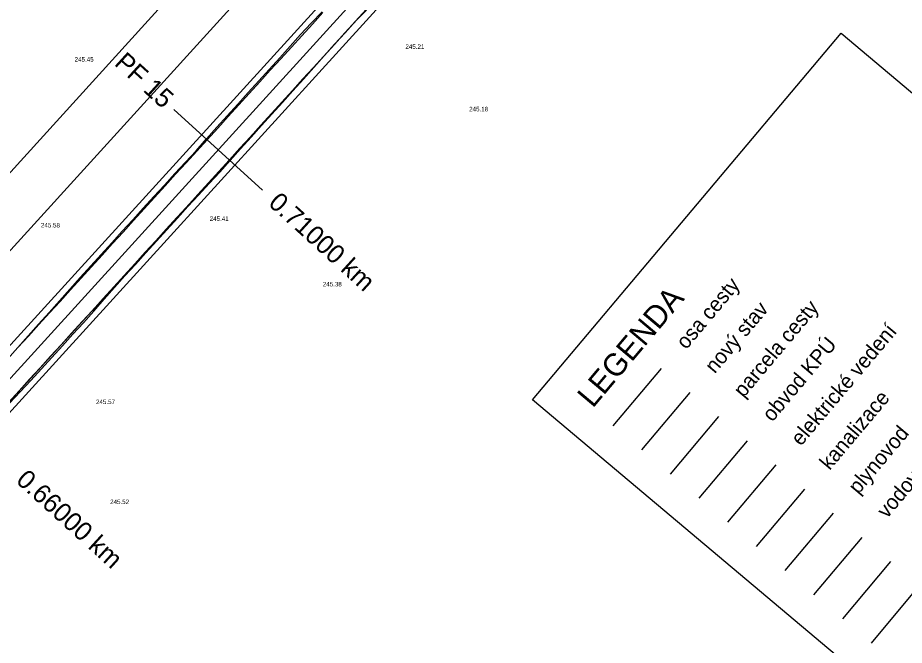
# Model space of a CAD drawing. Extents: x -555887 to -552101, y -1100251 to -1096546.
# Drawn here: x -554433.8 to -554315.6, y -1097133.2 to -1097049.5 of the extents above; entities that cross this region are included whole.
import ezdxf

# ---------------------------------------------------------------- set-up
doc = ezdxf.new("R2010")
doc.units = 0
for name, color, linetype in [('IP_návrh', 7, 'Continuous'), ('PARCELY_cesty', 7, 'Continuous'), ('POLYGONY_SITUACE_PF', 7, 'Continuous'), ('POLYGONY_SITUACE_PF_POPISY', 7, 'Continuous'), ('POLYGONY_SITUACE_PO', 7, 'Continuous'), ('ram_VC2', 7, 'Continuous'), ('Výškopis', 7, 'Continuous'), ('zájem', 7, 'Continuous')]:
    doc.layers.add(name, color=color, linetype=linetype)

msp = doc.modelspace()

# ---------------------------------------------------------------- linework, layer by layer
at = {"layer": 'IP_návrh'}
msp.add_line((-554875.9, -1097565.92), (-554275.99, -1096905.69), dxfattribs=at)
at = {"layer": 'PARCELY_cesty'}
for points in [[(-554879.07, -1097590.15), (-554550.67, -1097229.32), (-554531.76, -1097208.54), (-554275.81, -1096927.3), (-554273.04, -1096923.94), (-554268.63, -1096916.51), (-554265.12, -1096907.97), (-554264.18, -1096901.52)], [(-554875.85, -1097577.71), (-554629.16, -1097306.65), (-554626.42, -1097299.8), (-554612.94, -1097285.13), (-554606.19, -1097281.41), (-554359.61, -1097010.48), (-554356.78, -1097004.21), (-554343, -1096989.28), (-554337.66, -1096986.36), (-554280.34, -1096923.38), (-554277.96, -1096920.48), (-554274.11, -1096913.98), (-554271.59, -1096906.68), (-554270.35, -1096901.41)]]:
    msp.add_lwpolyline(points, dxfattribs=at)
at = {"layer": 'POLYGONY_SITUACE_PF'}
for p, q in [((-554412.99, -1097061.7), (-554407.07, -1097067.08)), ((-554407.07, -1097067.08), (-554401.16, -1097072.47))]:
    msp.add_line(p, q, dxfattribs=at)
at = {"layer": 'POLYGONY_SITUACE_PO'}
for p, q in [((-554884.96, -1097592.18), (-554278.08, -1096925.34)), ((-554878.71, -1097588.28), (-554338.29, -1096994.47)), ((-554394.68, -1097050.19), (-554393.24, -1097048.68)), ((-554394.53, -1097050.33), (-554393.13, -1097048.79)), ((-554394.53, -1097050.33), (-554393.13, -1097048.79)), ((-554388.77, -1097049.94), (-554387.37, -1097048.4)), ((-554388.76, -1097049.94), (-554387.3, -1097048.46)), ((-554390.17, -1097051.48), (-554388.77, -1097049.94)), ((-554390.14, -1097051.44), (-554388.76, -1097049.94)), ((-554396.11, -1097051.7), (-554394.68, -1097050.19)), ((-554395.93, -1097051.87), (-554394.53, -1097050.33)), ((-554395.93, -1097051.87), (-554394.53, -1097050.33)), ((-554397.5, -1097053.26), (-554396.11, -1097051.7)), ((-554397.33, -1097053.41), (-554395.93, -1097051.87)), ((-554397.33, -1097053.41), (-554395.93, -1097051.87)), ((-554391.57, -1097053.02), (-554390.17, -1097051.48)), ((-554391.56, -1097053.03), (-554390.19, -1097051.5)), ((-554390.19, -1097051.5), (-554390.17, -1097051.48)), ((-554390.17, -1097051.48), (-554390.14, -1097051.44)), ((-554398.88, -1097054.82), (-554397.5, -1097053.26)), ((-554398.74, -1097054.95), (-554397.33, -1097053.41)), ((-554398.74, -1097054.95), (-554397.33, -1097053.41)), ((-554392.97, -1097054.56), (-554391.57, -1097053.02)), ((-554392.95, -1097054.58), (-554391.56, -1097053.03)), ((-554394.38, -1097056.1), (-554392.97, -1097054.56)), ((-554394.34, -1097056.13), (-554392.95, -1097054.58)), ((-554400.27, -1097056.37), (-554398.88, -1097054.82)), ((-554400.14, -1097056.49), (-554398.74, -1097054.95)), ((-554400.14, -1097056.49), (-554398.74, -1097054.95)), ((-554401.68, -1097057.91), (-554400.27, -1097056.37)), ((-554401.54, -1097058.03), (-554400.14, -1097056.49)), ((-554401.54, -1097058.03), (-554400.14, -1097056.49)), ((-554395.78, -1097057.64), (-554394.38, -1097056.1)), ((-554395.73, -1097057.68), (-554394.34, -1097056.13)), ((-554403.08, -1097059.45), (-554401.68, -1097057.91)), ((-554402.94, -1097059.57), (-554401.54, -1097058.03)), ((-554402.94, -1097059.57), (-554401.54, -1097058.03)), ((-554397.18, -1097059.18), (-554395.78, -1097057.64)), ((-554397.12, -1097059.24), (-554395.73, -1097057.68)), ((-554404.48, -1097060.99), (-554403.08, -1097059.45)), ((-554398.58, -1097060.72), (-554397.18, -1097059.18)), ((-554398.51, -1097060.79), (-554397.12, -1097059.24)), ((-554404.35, -1097061.11), (-554402.94, -1097059.57)), ((-554404.35, -1097061.11), (-554402.94, -1097059.57)), ((-554405.88, -1097062.54), (-554404.48, -1097060.99)), ((-554405.75, -1097062.65), (-554404.35, -1097061.11)), ((-554405.75, -1097062.65), (-554404.35, -1097061.11)), ((-554399.99, -1097062.26), (-554398.58, -1097060.72)), ((-554399.92, -1097062.33), (-554398.51, -1097060.79)), ((-554407.27, -1097064.09), (-554405.88, -1097062.54)), ((-554407.15, -1097064.19), (-554405.75, -1097062.65)), ((-554407.15, -1097064.19), (-554405.75, -1097062.65)), ((-554401.39, -1097063.81), (-554399.99, -1097062.26)), ((-554401.31, -1097063.87), (-554399.92, -1097062.33)), ((-554408.65, -1097065.65), (-554407.27, -1097064.09)), ((-554408.55, -1097065.74), (-554407.15, -1097064.19)), ((-554408.55, -1097065.74), (-554407.15, -1097064.19)), ((-554402.79, -1097065.35), (-554401.39, -1097063.81)), ((-554402.71, -1097065.42), (-554401.31, -1097063.87)), ((-554404.19, -1097066.89), (-554402.79, -1097065.35)), ((-554410.03, -1097067.21), (-554408.65, -1097065.65)), ((-554409.95, -1097067.28), (-554408.55, -1097065.74)), ((-554409.95, -1097067.28), (-554408.55, -1097065.74)), ((-554404.1, -1097066.97), (-554402.71, -1097065.42)), ((-554411.44, -1097068.74), (-554410.03, -1097067.21)), ((-554411.36, -1097068.82), (-554409.95, -1097067.28)), ((-554411.36, -1097068.82), (-554409.95, -1097067.28)), ((-554405.59, -1097068.43), (-554404.19, -1097066.89)), ((-554405.5, -1097068.52), (-554404.1, -1097066.97)), ((-554412.85, -1097070.27), (-554411.44, -1097068.74)), ((-554412.76, -1097070.36), (-554411.36, -1097068.82)), ((-554412.76, -1097070.36), (-554411.36, -1097068.82)), ((-554407, -1097069.97), (-554405.59, -1097068.43)), ((-554406.88, -1097070.07), (-554405.5, -1097068.52)), ((-554408.4, -1097071.51), (-554407, -1097069.97)), ((-554408.3, -1097071.6), (-554406.88, -1097070.07)), ((-554414.27, -1097071.8), (-554412.85, -1097070.27)), ((-554414.16, -1097071.9), (-554412.76, -1097070.36)), ((-554414.16, -1097071.9), (-554412.76, -1097070.36)), ((-554415.68, -1097073.33), (-554414.27, -1097071.8)), ((-554415.56, -1097073.44), (-554414.16, -1097071.9)), ((-554415.56, -1097073.44), (-554414.16, -1097071.9)), ((-554409.8, -1097073.05), (-554408.4, -1097071.51)), ((-554409.71, -1097073.14), (-554408.3, -1097071.6)), ((-554417.09, -1097074.87), (-554415.68, -1097073.33)), ((-554416.97, -1097074.98), (-554415.56, -1097073.44)), ((-554416.97, -1097074.98), (-554415.56, -1097073.44)), ((-554411.2, -1097074.59), (-554409.8, -1097073.05)), ((-554411.12, -1097074.67), (-554409.71, -1097073.14)), ((-554412.61, -1097076.13), (-554411.2, -1097074.59)), ((-554412.52, -1097076.21), (-554411.12, -1097074.67)), ((-554418.49, -1097076.41), (-554417.09, -1097074.87)), ((-554418.37, -1097076.52), (-554416.97, -1097074.98)), ((-554418.37, -1097076.52), (-554416.97, -1097074.98)), ((-554419.88, -1097077.96), (-554418.49, -1097076.41)), ((-554419.77, -1097078.06), (-554418.37, -1097076.52)), ((-554419.77, -1097078.06), (-554418.37, -1097076.52)), ((-554414.01, -1097077.67), (-554412.61, -1097076.13)), ((-554413.93, -1097077.75), (-554412.52, -1097076.21)), ((-554421.28, -1097079.5), (-554419.88, -1097077.96)), ((-554421.17, -1097079.6), (-554419.77, -1097078.06)), ((-554421.17, -1097079.6), (-554419.77, -1097078.06)), ((-554415.41, -1097079.21), (-554414.01, -1097077.67)), ((-554415.33, -1097079.28), (-554413.93, -1097077.75)), ((-554422.69, -1097081.04), (-554421.28, -1097079.5)), ((-554416.81, -1097080.75), (-554415.41, -1097079.21)), ((-554416.74, -1097080.82), (-554415.33, -1097079.28)), ((-554422.58, -1097081.14), (-554421.17, -1097079.6)), ((-554422.58, -1097081.14), (-554421.17, -1097079.6)), ((-554418.21, -1097082.29), (-554416.81, -1097080.75)), ((-554424.09, -1097082.58), (-554422.69, -1097081.04)), ((-554423.98, -1097082.68), (-554422.58, -1097081.14)), ((-554423.98, -1097082.68), (-554422.58, -1097081.14)), ((-554418.13, -1097082.37), (-554416.74, -1097080.82)), ((-554425.49, -1097084.12), (-554424.09, -1097082.58)), ((-554425.38, -1097084.22), (-554423.98, -1097082.68)), ((-554425.38, -1097084.22), (-554423.98, -1097082.68)), ((-554419.62, -1097083.84), (-554418.21, -1097082.29)), ((-554419.53, -1097083.91), (-554418.13, -1097082.37)), ((-554426.88, -1097085.68), (-554425.49, -1097084.12)), ((-554426.78, -1097085.77), (-554425.38, -1097084.22)), ((-554426.78, -1097085.77), (-554425.38, -1097084.22)), ((-554421.02, -1097085.38), (-554419.62, -1097083.84)), ((-554420.92, -1097085.46), (-554419.53, -1097083.91)), ((-554422.42, -1097086.92), (-554421.02, -1097085.38)), ((-554422.3, -1097087.02), (-554420.92, -1097085.46)), ((-554428.26, -1097087.24), (-554426.88, -1097085.68)), ((-554428.18, -1097087.31), (-554426.78, -1097085.77)), ((-554428.18, -1097087.31), (-554426.78, -1097085.77)), ((-554429.65, -1097088.79), (-554428.26, -1097087.24)), ((-554429.59, -1097088.85), (-554428.18, -1097087.31)), ((-554429.59, -1097088.85), (-554428.18, -1097087.31)), ((-554423.82, -1097088.46), (-554422.42, -1097086.92)), ((-554423.66, -1097088.6), (-554422.3, -1097087.02)), ((-554431.04, -1097090.34), (-554429.65, -1097088.79)), ((-554430.99, -1097090.39), (-554429.59, -1097088.85)), ((-554430.99, -1097090.39), (-554429.59, -1097088.85)), ((-554425.23, -1097090), (-554423.82, -1097088.46)), ((-554425.06, -1097090.15), (-554423.66, -1097088.6)), ((-554426.63, -1097091.54), (-554425.23, -1097090)), ((-554426.46, -1097091.69), (-554425.06, -1097090.15)), ((-554432.43, -1097091.9), (-554431.04, -1097090.34)), ((-554432.39, -1097091.93), (-554430.99, -1097090.39)), ((-554432.39, -1097091.93), (-554430.99, -1097090.39)), ((-554433.82, -1097093.44), (-554432.43, -1097091.9)), ((-554433.79, -1097093.47), (-554432.39, -1097091.93)), ((-554433.79, -1097093.47), (-554432.39, -1097091.93)), ((-554428.03, -1097093.08), (-554426.63, -1097091.54)), ((-554427.87, -1097093.23), (-554426.46, -1097091.69)), ((-554435.2, -1097095.01), (-554433.79, -1097093.47)), ((-554435.2, -1097095.01), (-554433.79, -1097093.47)), ((-554429.43, -1097094.62), (-554428.03, -1097093.08)), ((-554429.27, -1097094.77), (-554427.87, -1097093.23)), ((-554430.83, -1097096.16), (-554429.43, -1097094.62)), ((-554430.67, -1097096.31), (-554429.27, -1097094.77)), ((-554432.24, -1097097.7), (-554430.83, -1097096.16)), ((-554432.08, -1097097.85), (-554430.67, -1097096.31)), ((-554433.64, -1097099.24), (-554432.24, -1097097.7)), ((-554433.5, -1097099.37), (-554432.08, -1097097.85)), ((-554435.04, -1097100.78), (-554433.64, -1097099.24)), ((-554434.93, -1097100.89), (-554433.5, -1097099.37))]:
    msp.add_line(p, q, dxfattribs=at)
at = {"layer": 'ram_VC2'}
for p, q in [((-554348.02, -1097096.24), (-554354.46, -1097103.89)), ((-554344.2, -1097099.46), (-554350.63, -1097107.11)), ((-554340.37, -1097102.68), (-554346.81, -1097110.33)), ((-554336.54, -1097105.9), (-554342.98, -1097113.55)), ((-554332.72, -1097109.12), (-554339.16, -1097116.77)), ((-554328.89, -1097112.34), (-554335.33, -1097119.99)), ((-554325.07, -1097115.56), (-554331.51, -1097123.21)), ((-554321.24, -1097118.78), (-554327.68, -1097126.43)), ((-554317.42, -1097121.99), (-554323.85, -1097129.65)), ((-554313.59, -1097125.21), (-554320.03, -1097132.87))]:
    msp.add_line(p, q, dxfattribs=at)
msp.add_lwpolyline([(-554365.16, -1097100.42), (-554324.01, -1097051.52), (-554255.08, -1097109.53), (-554296.23, -1097158.43)], close=True, dxfattribs=at)
at = {"layer": 'zájem'}
for points in [[(-554089.18, -1096729.49), (-554110.69, -1096747.36), (-554142.08, -1096773.53), (-554179.17, -1096807.62), (-554205.78, -1096822.41), (-554208.2, -1096823.7), (-554225.08, -1096837.14), (-554235.5, -1096849), (-554251.97, -1096867.91), (-554264.55, -1096882.42), (-554265.7, -1096883.76), (-554272.88, -1096891.67), (-554281.79, -1096901.5), (-554289.93, -1096910.44), (-554329.92, -1096954.43), (-554333.96, -1096958.92), (-554536.43, -1097182.04)], [(-554536.43, -1097182.04), (-554333.96, -1096958.92), (-554329.92, -1096954.43), (-554289.93, -1096910.44), (-554281.79, -1096901.5), (-554272.88, -1096891.67), (-554265.7, -1096883.76), (-554264.55, -1096882.42), (-554251.97, -1096867.91), (-554235.5, -1096849), (-554225.08, -1096837.14), (-554208.2, -1096823.7), (-554205.78, -1096822.41), (-554179.17, -1096807.62), (-554142.08, -1096773.53), (-554110.69, -1096747.36), (-554089.18, -1096729.49)]]:
    msp.add_lwpolyline(points, dxfattribs=at)

# ---------------------------------------------------------------- texts
at = {"layer": 'POLYGONY_SITUACE_PF_POPISY'}
for s, p in [('PF 15', (-554421.06, -1097055.71)), ('0.71000 km', (-554400.53, -1097074.39)), ('0.66000 km', (-554434.19, -1097111.36))]:
    msp.add_text(s, height=2.5, rotation=317.6947, dxfattribs=at).set_placement(p)
at = {"layer": 'ram_VC2'}
for s, height, p in [('osa cesty', 2, (-554344.68, -1097093.82)), ('LEGENDA', 3, (-554357.14, -1097101.64)), ('nový stav', 2, (-554340.86, -1097097.04)), ('parcela cesty', 2, (-554337.03, -1097100.26)), ('elektrické vedení', 2, (-554329.38, -1097106.7)), ('obvod KPÚ', 2, (-554333.2, -1097103.48)), ('kanalizace', 2, (-554325.55, -1097109.92)), ('plynovod', 2, (-554321.73, -1097113.14)), ('vodovod', 2, (-554317.9, -1097116.36))]:
    msp.add_text(s, height=height, rotation=49.9197, dxfattribs=at).set_placement(p)
at = {"layer": 'Výškopis'}
for s, p in [('245.21', (-554382.12, -1097053.63)), ('245.45', (-554426.23, -1097055.33)), ('245.18', (-554373.62, -1097061.96)), ('245.41', (-554408.22, -1097076.57)), ('245.58', (-554430.73, -1097077.45)), ('245.38', (-554393.14, -1097085.31)), ('245.57', (-554423.38, -1097101)), ('245.52', (-554421.5, -1097114.34))]:
    msp.add_text(s, height=0.6, dxfattribs=at).set_placement(p)

doc.saveas('drawing.dxf')
